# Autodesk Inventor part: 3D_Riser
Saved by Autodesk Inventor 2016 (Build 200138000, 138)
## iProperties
Created: 2016-01
Part Number: 3D_Riser
Material: Generic
Document SubType Name: Modeling
Designer: John
Density: 1 g/cm^3
Appearance: Default
Author: John
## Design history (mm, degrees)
feature "Base1"
sketch "Sketch1"
  geometry: L1 (0, 0)-(180, 0) reference; L2 (185, 5)-(185, 185) reference; L3 (180, 190)-(0, 190) reference; L4 (-5, 185)-(-5, 5) reference; L5 (22.142, 182)-(157.858, 182) reference; L6 (174.071, 169.929)-(164.929, 179.071) reference; L7 (177, 162.858)-(177, 27.142) reference; L8 (164.929, 10.929)-(174.071, 20.071) reference; L9 (157.858, 8)-(22.142, 8) reference; L10 (5.929, 20.071)-(15.071, 10.929) reference; L11 (3, 27.142)-(3, 162.858) reference; L12 (15.071, 179.071)-(5.929, 169.929) reference; C1 r 1.75 at (3, 182) reference; C2 r 1.75 at (177, 8) reference; C3 r 1.75 at (177, 182) reference; C4 r 1.75 at (3, 8) reference; A1 r 5 centre (0, 5) between (-5, 5) and (0, 0) reference; A2 r 5 centre (180, 5) between (180, 0) and (185, 5) reference; A3 r 5 centre (180, 185) between (185, 185) and (180, 190) reference; A4 r 5 centre (0, 185) between (0, 190) and (-5, 185) reference; A5 r 10 centre (157.858, 172) between (164.929, 179.071) and (157.858, 182) reference; A6 r 10 centre (167, 162.858) between (177, 162.858) and (174.071, 169.929) reference; A7 r 10 centre (167, 27.142) between (174.071, 20.071) and (177, 27.142) reference; A8 r 10 centre (157.858, 18) between (157.858, 8) and (164.929, 10.929) reference; A9 r 10 centre (22.142, 18) between (15.071, 10.929) and (22.142, 8) reference; A10 r 10 centre (13, 27.142) between (3, 27.142) and (5.929, 20.071) reference; A11 r 10 centre (13, 162.858) between (5.929, 169.929) and (3, 162.858) reference; A12 r 10 centre (22.142, 172) between (22.142, 182) and (15.071, 179.071) reference; 1 further point
extrude "Extrusion1" join sketch "Sketch1" distance "d0" = 6.35; taper "d1" = 0 deg
body "Solid1"
node "Projected Loop1"
